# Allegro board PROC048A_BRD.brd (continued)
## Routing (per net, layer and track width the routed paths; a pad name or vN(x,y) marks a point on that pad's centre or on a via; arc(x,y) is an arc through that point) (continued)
ETH_D3N: length 20.9
  TOP w0.102: U6.14 71.81,62.57 71.85,62.53 72.48,62.53 73.91,63.95 75.25,63.95 76.29,62.91 76.74,62.91 76.99,63.17 76.99,63.83 76.89,63.93 v1(76.73,63.93)
  BOTTOM w0.102: v1(76.73,63.93) 77.03,63.62 77.03,62.91 77.54,62.4 77.54,61.74 77.03,61.24 77.03,59.69 77.39,59.33 78.09,59.33 U17.9 U17.2 79.41,59.22 79.52,59.33 79.88,59.33 80.99,58.21 83.03,58.21 83.53,58.72 83.76,58.76 J6.4
ETH_D3P: length 20.9
  TOP w0.102: U6.13 71.77,62.07 71.85,62.15 72.5,62.15 74.02,63.67 75.14,63.67 76.18,62.63 76.85,62.63 77.27,63.05 77.27,63.58 v1(77.62,63.93)
  BOTTOM w0.102: J6.3 83.23,59.03 83.26,58.99 83.26,58.85 82.91,58.49 81.11,58.49 79.99,59.61 79.52,59.61 79.41,59.72 U17.1 U17.10 78.09,59.61 77.5,59.61 77.31,59.8 77.31,61.12 77.82,61.63 77.82,62.52 77.31,63.03 77.31,63.62 v1(77.62,63.93)
ETH_INT: length 36
  TOP w0.14: U6.60 67.63,53.29 69.32,51.6 R58.2 70.33,51.6 70.53,51.4 v1(70.53,50.95) ; U12.A15 v1(47.4,41.91)
  BOTTOM w0.14: v1(70.53,50.95) 70.05,50.95 68.55,49.45 66.9,49.45 65.63,50.72 59.66,50.72 58.07,49.13 50.2,49.13 48.24,47.18 48.24,43.37 47.4,42.53 v1(47.4,41.91)
FB1_REGA: length 4.7
  TOP w0.381: C5.2 R10.2 R18.1 31.99,89.33 31.34,89.33 30.94,88.94 U1.1
FB1_REGB: length 4.7
  TOP w0.381: U2.1 55.71,88.94 56.1,89.33 56.76,89.33 R19.1 R11.2 C6.2
FB2_REGA: length 4.1
  TOP w0.381: C10.2 R12.2 R13.1 U1.8
FB2_REGB: length 4.1
  TOP w0.381: U2.8 R15.1 R14.2 C11.2
FPGA_DDR3_CLK_IN_N: length 7.9
  TOP w0.14: U12.A5 39,43.31 38.19,44.12 36.67,44.12 35.99,44.79 R71.2 35.99,46.23 36.2,46.44 U8.5
FPGA_DDR3_CLK_IN_P: length 7.7
  TOP w0.14: U8.4 R71.1 35.15,44.87 36.39,43.63 37.66,43.63 38.2,43.09 U12.A4
FPGA_ERR_LED2: length 77.8
  TOP w0.14: v1(11.4,90.6) 11.4,92.5 11.72,92.82 LD5.1 ; U12.D10 v1(42.6,39.51)
  L03_SIG1 w0.107: v1(11.4,90.6) 11.4,90.22 27.53,74.09 42.89,74.09 43.91,73.07 43.91,58.34 43.58,58.01 43.58,42.39 43.43,42.23 43.43,41.31 43.43,39.95 42.99,39.51 v1(42.6,39.51)
FPGA_HOST_INT: length 45.2
  TOP w0.14: R97.1 7.95,34.19 7.59,33.83 v1(7.59,32.05) ; U12.M3 v1(37,32.31)
  L03_SIG1 w0.107: v1(7.59,32.05) 7.59,28.24 11.02,24.81 14.95,24.81 16.22,23.54 v1(28.29,23.54)
  L08_SIG2 w0.107: v1(28.29,23.54) 28.03,23.8 28.03,27.1 29.18,28.24 30.96,28.24 34.64,31.92 36.61,31.92 v1(37,32.31)
FPGA_MCU_RSTN: length 25.4
  TOP w0.14: U13.1 40.88,18.64 41.04,18.48 R147.2 41.53,18.22 41.39,18.08 v1(39.46,18.08) ; v1(33.88,19.86) 34.38,20.37 34.38,24.43 33.5,25.32 33.5,28.88 v1(34.38,29.76) ; U12.N3 v1(37,31.51)
  L08_SIG2 w0.107: v1(37,31.51) 35.25,31.51 34.38,30.65 v1(34.38,29.76)
  BOTTOM w0.14: v1(39.46,18.08) 38.45,19.1 34.64,19.1 v1(33.88,19.86)
FPGA_RST: length 80.5
  TOP w0.14: R161.1 R162.2 C96.2 v1(25.09,6.38) ; U12.R1 35.7,30.31 v1(35.34,29.96) ; LD13.1 4.41,34.15 v1(4.41,33.07)
  L03_SIG1 w0.107: v1(35.34,29.96) 35.78,29.51 35.78,29 35.27,28.49 35.27,27.73 34.77,27.22 34.77,22.02 33.24,20.49 32.99,20.49 27.16,14.67 27.16,8.45 v1(25.09,6.38)
  BOTTOM w0.14: v1(35.34,29.96) 34.45,29.07 31.91,29.07 30.32,27.48 30.32,23.41 28.8,21.89 20.02,21.89 17.48,19.35 11.78,19.35 4.41,26.72 v1(4.41,33.07)
FPGA_SPI_CS: length 29.7
  TOP w0.14: v1(26.76,41.45) 26.51,41.19 R86.1 ; U12.E13 v1(45.8,38.71)
  L08_SIG2 w0.107: v1(26.76,41.45) 26.76,43.61 29.69,46.53 35.91,46.53 39.8,42.64 39.8,39.24 39.92,39.11 41.22,39.11 41.38,38.95 41.38,38.59 41.64,38.33 45.42,38.33 v1(45.8,38.71)
FPGA_SPI_MISO: length 67.3
  TOP w0.14: v1(10.64,34.08) 11.01,33.7 R90.1 ; U12.D14 v1(46.6,39.51)
  L03_SIG1 w0.107: v1(10.64,34.08) 7.97,36.75 7.97,40.94 13.81,46.78 27.69,46.78 32.77,51.86 32.77,54.32 v1(33.24,54.8)
  BOTTOM w0.14: v1(33.24,54.8) 34.12,54.8 36.04,52.88 40.1,52.88 44.54,48.43 44.54,43.1 43.78,42.34 43.78,40.94 44.01,40.71 45.17,40.71 45.4,40.48 45.4,40.15 45.64,39.92 46.2,39.92 46.6,39.52 v1(46.6,39.51)
FPGA_SPI_MOSI: length 49.6
  TOP w0.14: U12.C14 v1(46.6,40.31) ; R99.1 29.79,36.14 29.56,36.37 28.29,36.37 27.78,36.88 27.78,44.62 32.73,49.58 32.73,55.42 v1(33.11,55.8)
  BOTTOM w0.14: v1(33.11,55.8) 35.02,55.8 36.06,54.76 40.88,54.76 45.69,49.96 45.69,43.1 46.2,42.59 46.2,40.72 v1(46.6,40.31)
FPGA_SPI_SCK: length 48.8
  TOP w0.14: U12.A14 v1(46.6,41.91) ; R92.1 27.27,36.52 27.27,46.4 31.46,50.59 31.46,55.79 v1(32.04,56.37)
  BOTTOM w0.14: v1(32.04,56.37) 36.36,56.37 36.8,55.93 41.12,55.93 46.83,50.21 46.83,43.23 46.6,43 v1(46.6,41.91)
FPGA_UART_RX: length 38.3
  TOP w0.14: R142.1 v1(28.42,18.34) ; U12.A13 v1(45.8,41.91)
  L03_SIG1 w0.107: v1(34.45,18.65) 36.67,20.87 36.67,25.04 38.22,26.59 38.22,30.07 38.44,30.3 38.72,30.3 38.98,30.56 38.98,37.23 39.26,37.51 42.74,37.51 43.15,37.92 43.15,38.2 44.08,39.13 44.36,39.13 45.38,40.16 45.38,41.49 v1(45.8,41.91)
  BOTTOM w0.14: v1(34.45,18.65) 33.88,19.22 29.3,19.22 v1(28.42,18.34)
FPGA_UART_TX: length 73.9
  TOP w0.14: v1(32.73,17.95) 33.08,18.3 R139.1 ; U12.B13 v1(45.8,41.11)
  L08_SIG2 w0.107: v1(32.73,17.95) 32.73,18.39 31.9,19.22 27.78,19.22 27.27,19.73 27.27,33.07 23.84,36.5 23.84,49.96 29.18,55.29 v1(32.18,55.29)
  BOTTOM w0.14: v1(45.8,41.11) 45.05,41.86 45.05,49.2 40.73,53.51 36.16,53.51 34.38,55.29 v1(32.18,55.29)
FT_FPGA_RF_EP_I2C_SCL: length 143.3
  TOP w0.14: U7.6 v1(36.16,55.42) R51.2 36.89,54.92 37.11,54.69 39.18,54.69 43.15,50.72 47.85,50.72 49.37,49.2 49.37,46.66 49.12,46.41 R68.2 48.61,45.74 48.62,45.73 R81.1 ; R141.1 26.04,18.84 26.42,19.22 29.3,19.22 v1(29.81,19.73) ; v1(78.71,93.01) 78.72,93 R3.1
  L08_SIG2 w0.107: v1(78.71,93.01) 77.31,91.61 73.25,91.61 68.04,86.41 68.04,83.23 67.02,82.22 51.15,82.22 44.29,75.36 40.86,75.36 36.8,71.29 36.8,57.96 36.16,57.32 v1(36.16,55.42) 36.67,54.91 36.67,52.88 35.43,51.64 28.19,51.64 24.73,48.18 24.73,37 27.78,33.96 27.78,21.76 v1(29.81,19.73)
FT_FPGA_RF_EP_I2C_SDA: length 139.1
  TOP w0.14: v1(36.16,54.15) U7.5 ; v1(36.16,54.15) 36.16,53.7 36.31,53.55 39.3,53.55 42.51,50.34 47.21,50.34 47.97,49.58 47.97,46.54 47.84,46.41 R67.2 47.34,45.92 47.35,45.91 R76.1 ; v1(36.16,54.15) 36.42,54.15 R52.2 ; R136.1 25.77,19.73 v1(28.03,19.73) ; v1(76.42,93.14) R4.1 R5.1
  L08_SIG2 w0.107: v1(28.03,19.73) 27.53,20.24 27.53,33.45 24.22,36.75 24.22,48.27 30.11,54.15 v1(36.16,54.15) 36.16,54.66 35.53,55.29 35.53,72.06 39.34,75.87 44.04,75.87 51.02,82.85 66.01,82.85 67.53,84.37 67.53,86.79 72.99,92.25 75.53,92.25 v1(76.42,93.14)
FTDI1_VDD_1V8: length 7.2
  TOP w0.305: U15.12 v1(78.64,15.99) ; U15.64 v1(75.47,7.35) ; U15.37 v1(64.85,15.99) ; U15.49 67.97,7.6 67.15,6.78 C97.1
  TOP w0.381: C97.1 66.64,6.84 v1(66.64,7.79)
FTDI1_VPHY: length 5.4
  TOP w0.33: U15.4 78.82,11.99 79.13,12.3 C88.1
  TOP w0.381: C88.1 C90.1 82.62,12.3 FB4.2
FTDI1_VPLL: length 6.1
  TOP w0.305: 79.19,14.83 79.19,14.75 78.86,14.42 78.39,14.42 78.31,14.49 U15.9
  TOP w0.381: 79.19,14.83 79.19,15.17 79.77,15.75 C86.1 C85.1 FB3.2
FTDI2_VCORE: length 12.3
  TOP w0.254: U3.37 C15.1 70.95,86.03 71.34,86.41 v1(71.6,86.41) ; v1(74.77,76.25) 74.1,76.25 C32.1 74.03,76.65 74.7,77.32 U3.49 ; C14.1 85.98,86.44 84.99,85.45 U3.12 ; U3.64 82.2,77.58 82.94,76.84 C30.1
  TOP w0.381: v1(86.96,87.04) 86.58,86.66 86.32,86.66 C14.1 ; v1(82.26,76.37) C30.1
FTDI2_VPHY: length 5.3
  TOP w0.254: C23.1 85.73,81.02 85.31,81.45 U3.4
  TOP w0.381: C23.1 86.38,80.97 C24.1 88.91,80.97 89.07,80.81 FB2.2
FTDI2_VPLL: length 5.4
  TOP w0.254: U3.9 85.46,83.95 85.9,84.38 C17.1
  TOP w0.381: C17.1 86.46,84.38 86.74,84.66 C16.1 FB1.2
FTDI_HOST_INT: length 104
  TOP w0.14: v1(8.22,33.32) 8.5,33.05 R100.1 ; R6.1 71.14,92.17 70.61,91.65 R22.1 v1(66.9,87.79)
  L08_SIG2 w0.107: v1(66.9,87.79) 52.53,87.79 43.53,78.79 36.54,78.79 26.38,68.63 26.38,56.69 20.41,50.72 20.41,42.21 11.52,33.32 v1(8.22,33.32)
FTDI_JTAG_ACT: length 70.2
  TOP w0.14: v1(7.73,12.99) 8.28,12.99 LD15.1 ; U15.21 v1(73.47,18.74)
  BOTTOM w0.14: v1(73.47,18.74) 72.68,17.95 41.24,17.95 36.92,13.64 8.38,13.64 v1(7.73,12.99)
FTDI_JTAG_TCK: length 73.5
  TOP w0.14: TP9.1 90.26,20.8 89.46,20 R135.1 88.82,19.34 R140.2 ; U12.T5 v1(38.6,29.11)
  L08_SIG2 w0.107: v1(38.6,29.11) 39,29.51 40.48,29.51 40.61,29.38 40.61,24.68 40.92,24.38 76.62,24.38 79.47,27.22 84.8,27.22 85.18,27.61 87.85,27.61 88.64,26.82 88.64,24.08 TP9.1
FTDI_JTAG_TDI: length 56.5
  TOP w0.14: R124.2 v1(78.45,22.14) ; U12.R5 v1(38.6,29.91) ; R133.1 TP7.1
  L08_SIG2 w0.107: v1(78.45,22.14) 76.17,22.14 74.26,24.05 40.61,24.05 39.82,24.84 39.82,28.43 39.56,28.7 38.48,28.7 38.22,28.96 38.22,29.53 v1(38.6,29.91)
  BOTTOM w0.14: v1(78.45,22.14) 79.6,21 82.47,21 TP7.1
FTDI_JTAG_TDO: length 62
  TOP w0.14: R121.2 78.38,23.29 79.02,23.92 v1(79.47,23.92) 85.62,23.92 TP8.1 R134.1 ; U12.V4 v1(37.8,27.51)
  L08_SIG2 w0.107: v1(79.47,23.92) 79.34,23.8 79.34,21.76 78.33,20.75 74.01,20.75 72.1,22.65 54.07,22.65 53.31,23.41 39.08,23.41 38.38,24.12 38.38,25.27 38.22,25.42 38.22,27.1 v1(37.8,27.51)
FTDI_JTAG_TMS: length 55.9
  TOP w0.14: R118.2 R115.1 TP1.1 ; U12.U5 v1(38.6,28.31)
  L08_SIG2 w0.107: v1(38.6,28.31) 38.98,27.93 38.98,25.41 38.83,25.26 38.83,24.3 39.34,23.8 53.82,23.8 54.63,22.98 73.05,22.98 74.77,21.26 78.18,21.26 78.89,21.97 78.89,25.12 79.39,25.62 TP1.1
FTDI_MCU_RSTN: length 109.7
  TOP w0.14: U13.2 41.09,19.14 41.57,19.61 R144.2 41.57,20.55 41.37,20.75 35.02,20.75 34.77,21 34.77,24.56 33.88,25.45 33.88,28.75 34.13,29 34.38,29 34.84,29.46 34.84,32.23 v1(34.51,32.56) ; R26.1 67.97,80.9 v1(67.08,80.02)
  L08_SIG2 w0.107: v1(67.08,80.02) 50.98,80.02 39.03,68.07 39.03,57.74 39.04,57.73 39.04,53.87 39.03,53.86 39.03,51.17 36.16,48.31 29.05,48.31 25.75,45 25.75,40.69 26.13,40.31 26.13,37.13 28.54,34.72 31.97,34.72 34.13,32.56 v1(34.51,32.56)
FTDI_UART_RXD: length 107.7
  TOP w0.14: U3.38 71.92,84.95 71.34,84.37 67.02,84.37 v1(66.77,84.63) ; v1(29.18,17.95) 28.54,17.32 27.8,17.32 R146.1
  L08_SIG2 w0.107: v1(29.18,17.95) 28.67,17.95 28.54,17.83 27.91,17.83 27.02,18.72 27.02,32.43 23.46,35.99 23.46,50.59 29.56,56.69 29.56,67.23 38.83,76.5 43.78,76.5 50.77,83.49 65.63,83.49 v1(66.77,84.63)
FTDI_UART_TXD: length 112.3
  TOP w0.14: v1(65.5,84.63) 66.29,83.84 71.44,83.84 72.05,84.45 U3.39 ; R138.1 32.48,18.72 v1(31.97,18.21)
  L08_SIG2 w0.107: v1(65.5,84.63) 65.19,84.94 51.33,84.94 43.53,77.14 38.58,77.14 28.42,66.98 28.42,56.94 22.32,50.85 22.32,36.37 26.76,31.92 26.76,18.59 27.91,17.45 31.21,17.45 v1(31.97,18.21)
FTDI_USB1_DM: length 21.3
  TOP w0.102: J4.2 97.02,22.58 96.8,22.8 96.43,22.8 96.42,22.8 96.28,22.8 96.04,22.56 D11.1 95.57,22.56 95.49,22.63 95.37,22.63 93.87,21.13 92.93,21.13 90.43,18.63 88.4,18.63 83.79,14.02 80.88,14.02 80.78,13.92 R152.1
FTDI_USB1_DM_C: length 3
  TOP w0.102: R152.2 79.94,13.83 79.84,13.93 79.48,13.93 79.38,13.93 79.09,13.63 78.49,13.63 78.35,13.49 U15.7
FTDI_USB1_DP: length 21.2
  TOP w0.102: R150.1 81.2,14.23 83.7,14.23 88.31,18.84 90.34,18.84 92.84,21.34 93.78,21.34 95.34,22.91 95.34,23.03 95.57,23.26 D11.2 96.04,23.26 96.28,23.01 96.51,23.01 96.52,23.01 96.8,23.01 97.02,23.23 J4.3
FTDI_USB1_DP_C: length 3.1
  TOP w0.102: U15.8 78.35,13.99 78.49,13.85 79,13.85 79.32,14.17 79.84,14.17 79.94,14.27 R150.2
FTDI_USB2_DM: length 20.2
  TOP w0.102: R24.1 88.36,82.98 91.28,82.98 92.46,81.8 92.46,75.83 94.84,73.45 94.84,72.34 95.08,72.1 95.08,71.95 95.31,71.72 D9.1 95.52,71.72 95.85,72.06 96.04,72.06 96.15,71.95 96.15,71.2 96.44,70.91 96.83,70.91 97.02,70.73 J1.2
FTDI_USB2_DM_C: length 3.3
  TOP w0.102: R24.2 86.73,82.85 86.02,82.85 85.78,83.09 85,83.09 84.86,82.95 U3.7
FTDI_USB2_DP: length 19.9
  TOP w0.102: J1.3 97.02,71.38 96.77,71.13 96.53,71.13 96.36,71.29 96.36,72.04 96.13,72.27 95.64,72.27 95.49,72.42 D9.2 95.33,72.42 95.26,72.35 95.14,72.35 95.05,72.43 95.05,73.54 92.68,75.92 92.68,81.89 91.37,83.19 88.27,83.19 R23.1
FTDI_USB2_DP_C: length 3.5
  TOP w0.102: R23.2 87.05,83.19 86.92,83.07 86.11,83.07 85.87,83.31 85,83.31 84.86,83.45 U3.8
GPIO_PHY_RESETN: length 32.8
  TOP w0.14: 68.48,51.54 67.98,51.54 67.79,51.35 67.79,49.83 v1(66.9,48.94) ; 68.48,51.54 68.48,51.93 67.15,53.26 67.15,54.1 U6.59 ; 68.48,51.54 R57.2 ; U12.A16 48.2,41.91 v1(48.2,42.59)
  BOTTOM w0.14: v1(66.9,48.94) 64.48,48.94 64.1,49.32 64.1,49.96 63.72,50.34 60.55,50.34 58.26,48.05 50.39,48.05 49.24,46.91 49.24,43.48 48.35,42.59 v1(48.2,42.59)
HEADER_ERR_LED4: length 75.2
  TOP w0.14: LD8.1 v1(17.37,93.65) ; U12.B11 v1(44.2,41.11)
  L03_SIG1 w0.107: v1(44.2,41.11) 44.54,41.45 44.54,41.71 45.56,42.73 45.56,57.32 46.11,57.88 46.11,74.42 43.02,77.52 29.18,77.52 16.86,89.84 16.86,93.14 v1(17.37,93.65)
HOST_INT: length 7.5
  TOP w0.14: R100.2 R97.2 10.31,34.59 12.92,34.59 13.98,33.54 J3.10
INITN: length 128.9
  TOP w0.14: LD12.1 3.74,38.74 3.65,38.65 v1(3.27,38.65) ; R111.2 87.75,27.63 87.09,26.97 TP3.1 ; U12.V3 v1(37,27.51)
  L08_SIG2 w0.107: v1(37,27.51) 36.62,27.13 36.62,22.96 38.07,21.51 39.85,21.51 40.48,20.87 55.63,20.87 56.26,21.51 64.99,21.51 67.28,19.22 83.66,19.22 85.57,21.13 85.57,25.45 85.74,25.62 TP3.1
  BOTTOM w0.14: v1(3.27,38.65) 3.02,38.4 3.02,22.4 4.41,21 8.73,21 11.14,18.59 18,18.59 20.16,20.75 29.94,20.75 30.7,19.99 33.24,19.99 35.02,21.76 35.02,25.07 36.27,26.32 37.17,26.32 37.4,26.55 37.4,27.11 v1(37,27.51)
LED_ACTN: length 34.2
  TOP w0.14: U6.61 68.13,53.3 69.18,52.24 70.45,52.24 71.98,50.72 77.82,50.72 v1(78.71,51.61)
  L08_SIG2 w0.107: v1(78.71,51.61) 78.71,50.72 82.52,46.91 94.33,46.91 95.52,48.1 95.52,49.71 J6.12
LED_LINKN: length 40.1
  TOP w0.14: v1(77.82,52.5) 76.68,51.35 71.98,51.35 70.71,52.62 69.31,52.62 68.63,53.3 U6.62
  L08_SIG2 w0.107: v1(77.82,52.5) 79.09,53.77 79.09,63.04 82.01,65.96 92.42,65.96 93.49,64.89 J6.13
LED_SPEED: length 5.5
  TOP w0.14: U6.63 69.13,53.31 69.44,53.01 71.42,53.01 v1(71.93,52.5)
  BOTTOM w0.14: v1(71.93,52.5) 72.23,52.19 TP12.1
LVDS_0M: length 48.6
  TOP w0.102: U12.E3 v1(37,38.71) ; J3.58 14.93,21.54 14.7,21.76 13.18,21.76 12.79,21.38 v1(12.79,21.3)
  BOTTOM w0.102: v1(37,38.71) 36.86,38.86 36.71,38.86 36.43,39.14 35.92,39.14 35.77,39.29 35.44,39.29 R203.2 34.88,39.26 32.6,39.26 26.27,32.94 23.86,32.94 21.45,30.53 13.19,30.53 12.16,29.5 12.16,28.11 12.92,27.35 12.92,25.57 13.56,24.94 15.72,24.94 16.35,24.3 16.35,22.14 15.97,21.76 12.39,21.76 12.29,21.66 12.29,21.4 12.39,21.3 v1(12.79,21.3)
LVDS_0P: length 48.6
  TOP w0.102: J3.56 14.82,22.04 14.82,22.04 12.97,22.04 v1(12.79,22.22) ; U12.F4 v1(37.8,37.91)
  BOTTOM w0.102: v1(12.79,22.22) 12.97,22.04 15.85,22.04 16.07,22.26 16.07,24.19 15.6,24.66 13.44,24.66 12.64,25.46 12.64,27.24 11.88,28 11.88,29.61 13.07,30.81 21.33,30.81 23.74,33.22 26.16,33.22 32.48,39.54 34.85,39.54 R203.1 35.41,39.57 35.88,39.57 36.04,39.42 36.54,39.42 36.83,39.14 37.12,39.14 37.38,38.87 37.38,38.34 v1(37.8,37.91)
LVDS_1M: length 48.8
  TOP w0.102: v1(13.56,22.85) 13.84,23.14 14.7,23.14 14.8,23.04 J3.52 ; U12.D5 v1(38.6,39.51)
  BOTTOM w0.102: v1(38.6,39.51) 38.47,39.64 38.47,40.17 36.05,42.59 35.31,42.59 R198.2 34.88,42.49 34.64,42.51 33.42,42.51 32.51,41.6 32.24,41.6 28.68,38.05 28.05,38.05 24.97,34.97 21.16,34.97 20.11,33.92 12.36,33.92 9.59,31.15 9.59,25.84 11.54,23.9 11.79,23.9 12.68,23.01 13.41,23.01 v1(13.56,22.85)
LVDS_1P: length 48.9
  TOP w0.102: U12.E4 v1(37.8,38.71) ; J3.50 14.8,23.54 14.68,23.41 13.68,23.41 13.56,23.54 v1(13.56,23.72)
  BOTTOM w0.102: v1(37.8,38.71) 38.19,39.11 38.19,40.05 35.93,42.31 35.54,42.31 R198.1 34.85,42.21 34.62,42.23 33.53,42.23 32.62,41.32 32.35,41.32 28.8,37.77 28.16,37.77 25.09,34.69 21.28,34.69 20.22,33.64 12.48,33.64 9.87,31.03 9.87,25.95 11.65,24.18 11.91,24.18 12.79,23.29 13.46,23.29 13.56,23.39 v1(13.56,23.72)
LVDS_2M: length 49
  TOP w0.102: v1(9.24,24.98) 9.24,24.91 9.14,24.81 8.9,24.81 8.76,24.96 8.76,25.47 9.09,25.8 12.77,25.8 13.11,26.15 14.69,26.15 14.8,26.04 J3.40 ; U12.E1 35.8,38.58 35.42,38.96 35.42,39.27 34.14,40.55 33.4,40.55 R84.2 32.83,40.55 32.45,40.55 31.43,41.58 31.27,41.58 v1(30.96,41.26)
  BOTTOM w0.102: v1(9.24,24.98) 9.11,24.84 8.96,24.84 8.73,25.08 8.73,31.03 13.3,35.61 24.35,35.61 28.39,39.65 29.17,39.65 30.47,40.95 30.47,41.45 30.57,41.55 30.85,41.55 30.96,41.45 v1(30.96,41.26)
LVDS_2P: length 49
  TOP w0.102: v1(30.96,42.12) 31.22,41.86 31.54,41.86 32.57,40.83 32.83,40.83 R84.1 33.4,40.83 34.26,40.83 35.59,39.49 35.96,39.49 36.34,39.11 U12.D2 ; J3.38 14.8,26.54 14.69,26.43 13,26.43 12.65,26.08 8.97,26.08 8.48,25.59 8.48,25.14 v1(8.31,24.98)
  BOTTOM w0.102: v1(30.96,42.12) 30.66,41.83 30.46,41.83 30.19,41.56 30.19,41.07 29.05,39.92 28.27,39.92 24.24,35.89 13.19,35.89 8.45,31.15 8.45,25.12 v1(8.31,24.98)
LVDS_3M: length 48.9
  TOP w0.102: J3.34 14.8,27.54 14.69,27.65 13.06,27.65 11.32,29.38 8.2,29.38 8.1,29.28 8.1,28.37 8.32,28.14 10.48,28.14 10.89,27.73 10.89,26.97 11.02,26.84 11.3,26.84 v1(11.34,26.88) ; U12.D3 v1(37,39.51)
  BOTTOM w0.102: v1(37,39.51) 36.72,39.8 36.4,39.8 35.79,40.41 34.9,40.41 34.47,40.84 34.33,40.84 R200.2 33.72,40.8 33.48,40.8 33.09,40.41 32.6,40.41 26.02,33.83 22.7,33.83 21.53,32.66 14.18,32.66 10.89,29.37 10.89,26.88 11.04,26.73 11.19,26.73 v1(11.34,26.88)
LVDS_3P: length 48.9
  TOP w0.102: J3.32 14.8,28.04 14.69,27.93 13.18,27.93 11.44,29.66 8.08,29.66 7.82,29.4 7.82,28.25 8.21,27.86 10.37,27.86 10.61,27.62 10.61,27.05 v1(10.44,26.88) ; U12.C3 v1(37,40.31)
  BOTTOM w0.102: v1(10.44,26.88) 10.61,27.05 10.61,29.49 14.06,32.94 21.42,32.94 22.59,34.11 25.9,34.11 32.48,40.69 32.97,40.69 33.48,41.19 33.84,41.19 R200.1 34.17,41.19 34.51,41.19 35.02,40.69 35.91,40.69 36.52,40.08 36.77,40.08 v1(37,40.31)
LVDS_12BIT_MODE_ON: length 73.6
  TOP w0.14: U12.A6 39.8,51.65 38.62,52.83 36.63,52.83 36.16,52.37 v1(35.53,52.37) ; v1(7.84,82.85) SW1.1
  L03_SIG1 w0.107: v1(35.53,52.37) 35.53,55.8 32.99,58.34 23.34,58.34 12.54,69.13 7.84,69.13 3.9,73.07 3.9,82.09 4.67,82.85 v1(7.84,82.85)
  BOTTOM w0.14: R223.1 6.23,83.47 6.85,82.85 v1(7.84,82.85)
LVDS_14BIT_MODE_ON: length 62.7
  TOP w0.14: v1(33.75,62.28) 33.8,62.23 33.8,45.46 36.06,43.21 37.02,43.21 37.8,42.43 37.8,41.35 38.03,41.12 39.4,41.12 U12.B6 ; SW1.2 v1(8.48,81.58)
  L03_SIG1 w0.107: v1(33.75,62.28) 33.5,62.28 14.83,80.95 10,80.95 9.37,81.58 v1(8.48,81.58)
  BOTTOM w0.14: R222.1 v1(8.48,81.58)
LVDS_16BIT_MODE_ON: length 72.7
  TOP w0.14: U12.D7 v1(40.2,39.51) ; SW1.3 v1(7.97,80.31)
  L03_SIG1 w0.107: v1(40.05,60.4) 40.05,68.43 37.69,70.79 26,70.79 14.57,82.22 8.08,82.22 7.71,81.86 7.71,80.56 v1(7.97,80.31)
  L08_SIG2 w0.107: v1(40.2,39.51) 40.2,39.52 40.58,39.9 40.58,42.89 40.05,43.43 v1(40.05,60.4)
  BOTTOM w0.14: R224.1 v1(7.97,80.31)
LVDS_CAPTURE: length 55.2
  TOP w0.14: SW2.1 13.94,72.65 14.08,72.79 v1(14.45,72.79) ; U12.E8 v1(41,38.71)
  L03_SIG1 w0.107: v1(14.45,72.79) 14.19,72.54 14.19,69.01 23.84,59.36 34,59.36 37.18,56.18 37.18,53.13 36.54,52.5 36.54,43.71 39.82,40.43 39.82,40.16 40.04,39.93 40.35,39.93 40.61,39.67 40.61,39.11 v1(41,38.71)
  BOTTOM w0.14: R173.2 13.94,72.65 14.08,72.79 v1(14.45,72.79)
LVDS_CLKM: length 49.1
  TOP w0.102: U12.F3 v1(37,37.91) ; v1(11.59,23.19) 11.27,23.19 11.17,23.29 11.17,23.95 11.98,24.76 14.63,24.76 14.85,24.54 J3.46
  BOTTOM w0.102: v1(37,37.91) 36.74,37.65 36.48,37.65 35.99,37.16 35.54,37.16 R208.2 34.73,37.13 32.48,37.13 25.49,30.15 25.49,23.33 25.39,23.23 24.83,23.23 24.73,23.33 24.73,24.44 24.47,24.7 23.8,24.7 23.54,24.44 23.54,23.36 23.21,23.03 18.75,23.03 16.21,20.49 11.91,20.49 11.17,21.23 11.17,23.09 11.3,23.21 11.56,23.21 v1(11.59,23.19)
LVDS_CLKP: length 49.1
  TOP w0.102: v1(10.72,23.19) 10.89,23.35 10.89,24.06 11.86,25.04 J3.44 ; U12.G3 v1(37,37.11)
  BOTTOM w0.102: v1(10.72,23.19) 10.89,23.02 10.89,21.11 11.79,20.21 16.33,20.21 18.87,22.75 23.32,22.75 23.82,23.25 23.82,24.32 23.92,24.42 24.35,24.42 24.45,24.32 24.45,23.22 24.72,22.95 25.51,22.95 25.77,23.22 25.77,30.03 32.6,36.85 35.01,36.85 R208.1 35.31,36.88 36.1,36.88 36.6,37.37 36.74,37.37 v1(37,37.11)
LVDS_FRCLKN: length 49.1
  TOP w0.102: v1(13.56,28.75) 13.56,29.03 13.66,29.13 15.59,29.13 J3.28 ; U12.E2 v1(36.2,38.71)
  BOTTOM w0.102: v1(36.2,38.71) 35.94,38.45 33.61,38.45 R204.2 33.09,38.41 32.62,38.41 24.58,30.37 24.58,28.98 24.22,28.62 22.94,28.62 22.42,28.1 22.42,24.55 22.08,24.2 20.92,24.2 20.67,24.46 20.67,26.34 20.29,26.72 19.51,26.72 19.14,26.35 19.14,24.43 18.92,24.2 17.6,24.2 17.37,24.43 17.37,29.5 16.97,29.89 15.57,29.89 15.21,29.53 15.21,28.11 15.08,27.99 13.43,27.99 13.02,28.39 13.02,29.16 13.12,29.26 13.81,29.26 13.91,29.16 13.91,29.01 13.65,28.75 v1(13.56,28.75)
LVDS_FRCLKP: length 49
  TOP w0.102: v1(13.56,29.72) 13.56,29.63 13.77,29.43 15.57,29.43 J3.26 ; U12.F2 v1(36.2,37.91)
  BOTTOM w0.102: v1(13.56,29.72) 13.38,29.54 13.01,29.54 12.74,29.27 12.74,28.28 13.31,27.71 15.2,27.71 15.49,28 15.49,29.41 15.69,29.61 16.86,29.61 17.09,29.38 17.09,24.32 17.48,23.92 19.03,23.92 19.42,24.32 19.42,26.23 19.63,26.44 20.17,26.44 20.39,26.22 20.39,24.34 20.81,23.92 22.19,23.92 22.7,24.43 22.7,27.99 23.06,28.34 24.34,28.34 24.86,28.86 24.86,30.26 32.74,38.13 33.09,38.13 R204.1 33.69,38.17 36.03,38.17 36.2,38.01 v1(36.2,37.91)
LVDS_PATH_ERR_LED3: length 74.5
  TOP w0.14: U12.A11 v1(44.2,41.91) ; LD7.1 v1(14.19,93.65)
  L03_SIG1 w0.107: v1(14.19,93.65) 14.95,92.88 14.95,90.47 29.05,76.37 42.89,76.37 45.24,74.02 45.24,42.96 v1(44.2,41.91)
LVDS_VALIDM: length 48.8
  TOP w0.102: v1(10.76,30.35) 11.06,30.65 14.69,30.65 14.8,30.54 J3.22 ; U12.B3 37.4,40.98 37.02,41.36 37.02,41.97 36.56,42.44 33.38,42.44 R82.2 32.85,42.44 32.49,42.44 v1(32.19,42.13)
  L03_SIG1 w0.089: v1(10.76,30.35) 10.94,30.53 15.33,30.53 15.59,30.79 15.59,32.05 15.68,32.14 16.24,32.14 16.33,32.05 16.33,30.79 16.63,30.49 17.61,30.49 18.13,31 18.13,42.34 19.24,43.45 30.45,43.45 31.6,42.3 32.02,42.3 v1(32.19,42.13)
LVDS_VALIDP: length 48.8
  TOP w0.102: v1(10.76,31.22) 11.06,30.93 14.69,30.93 14.8,31.04 J3.20 ; v1(32.19,43.02) 32.49,42.72 32.82,42.72 R82.1 33.41,42.72 36.67,42.72 37.31,42.08 37.31,41.61 U12.A3
  L03_SIG1 w0.089: v1(10.76,31.22) 10.76,30.91 10.85,30.82 15.21,30.82 15.3,30.91 15.3,32.17 15.56,32.43 16.36,32.43 16.62,32.17 16.62,30.91 16.75,30.78 17.49,30.78 17.84,31.12 17.84,42.46 19.12,43.74 30.57,43.74 31.72,42.59 31.84,42.59 32.19,42.94 v1(32.19,43.02)
MCU_RSTN: length 20.3
  TOP w0.14: J3.59 22.67,21.04 22.83,20.87 22.83,17.83 24.35,16.3 30.35,16.3 30.73,16.68 32.73,16.68 34.13,18.08 34.64,18.08 35.15,18.59 35.15,19.35 35.43,19.64 R143.2
MDIO_MDC: length 40.7
  TOP w0.14: v1(68.18,64.34) 68.18,64.68 68.13,64.73 U6.20 ; v1(46.32,45.87) 46.2,45.74 R75.1
  L08_SIG2 w0.107: v1(46.32,45.87) 45.81,46.38 45.81,48.05 46.83,49.07 46.83,59.99 50.39,63.55 53.82,63.55 54.61,64.34 v1(68.18,64.34)
  BOTTOM w0.14: v1(68.18,64.34) R183.2
MDIO_MDIO: length 47.2
  TOP w0.14: v1(46.33,49.7) 46.33,49.08 43.91,46.66 R73.1 ; U6.21 67.66,65.55 67.66,66.46 v1(68.18,66.98)
  L08_SIG2 w0.107: v1(46.33,49.7) 46.33,65.25 46.67,65.58 66.78,65.58 v1(68.18,66.98)
  BOTTOM w0.14: R181.2 68.34,65.78 68.18,65.95 v1(68.18,66.98)
MEM_VREF: length 5.8
  TOP w0.356: U10.J8 v1(61.09,38.08) ; U10.E1 v1(66.69,34.88) ; U11.E1 v1(78.5,34.88) ; U11.J8 v1(72.1,38.88)
  BOTTOM w0.33: 72.63,38.91 72.13,38.91 v1(72.1,38.88)
  BOTTOM w0.381: v1(61.09,38.08) 61.13,38.13 C140.2 ; v1(78.5,34.88) 78.64,35.02 79.44,35.02 C162.2 ; C139.1 72.63,38.91 ; C159.1 67.36,34.88 v1(66.69,34.88)
  vias: v1(86.33,44.75) v1(86.33,43.86)
OSC_CLKEN: length 15.7
  TOP w0.14: v1(39.31,43.86) 39.31,51.16 38.82,51.65 R54.1 ; U12.E5 v1(38.6,38.71)
  BOTTOM w0.14: v1(38.6,38.71) 39,39.11 39,41.15 38.19,41.96 38.19,43.58 38.47,43.86 v1(39.31,43.86)
PG: length 1.5
  BOTTOM w0.14: R201.2 93.69,39.6 93.81,39.48 U19.9
PGOOD: length 10.8
  TOP w0.14: v1(29.05,32.56) 29.05,33.44 28.66,33.83 R98.1 ; U12.L2 v1(36.2,33.11)
  BOTTOM w0.14: v1(36.2,33.11) 35.14,32.05 34.08,32.05 33.57,32.56 v1(29.05,32.56)
PHY_JTAG_RESET: length 3
  TOP w0.14: U6.24 66.08,65.57 66.08,66.38 65.87,66.59 65.25,66.59 64.99,66.85 64.99,67.48 65.04,67.53 R39.1
PROGRAMN: length 115.3
  TOP w0.14: v1(3.4,39.67) 3.4,40.63 3.54,40.77 LD11.1 ; R132.2 TP6.1 ; R114.1 R117.2 C81.2 3.63,22.68 v1(3.97,22.34) ; U12.W3 v1(37,26.71)
  L08_SIG2 w0.107: v1(37,26.71) 37.43,26.28 37.43,24.43 38.9,22.96 52.87,22.96 53.59,22.24 67.56,22.24 69.56,20.24 78.53,20.24 TP6.1
  BOTTOM w0.14: v1(37,26.71) 36.6,27.11 35.03,27.11 34.51,26.59 34.51,21.76 33.37,20.62 31.21,20.62 30.7,21.13 19.91,21.13 17.75,18.97 11.27,18.97 7.71,22.53 4.67,22.53 4.48,22.34 v1(3.97,22.34) 3.78,22.53 3.78,39.29 v1(3.4,39.67)
RAW_MODE: length 57
  TOP w0.14: SW2.4 10.13,72.56 10.36,72.79 v1(10.84,72.79) ; U12.C8 v1(41,40.31)
  L03_SIG1 w0.107: v1(41,40.31) 40.62,40.69 40.62,41.26 40.35,41.53 40.02,41.53 38.19,43.35 38.19,43.86 38.07,43.99 38.07,57.83 35.78,60.12 30.83,60.12 16.86,74.09 12.13,74.09 v1(10.84,72.79)
  BOTTOM w0.14: v1(10.84,72.79) 10.36,72.79 10.13,72.56 R176.2
RF_CONN_SPI_CS: length 110.1
  TOP w0.14: U3.19 81.2,88.29 v1(81.18,88.26) ; R85.1 v1(25.37,47.8)
  L08_SIG2 w0.107: v1(25.37,47.8) 28.32,50.75 35.05,50.75 37.31,53.01 37.31,71.04 41.12,74.85 44.54,74.85 51.15,81.45 67.15,81.45 68.67,82.98 68.67,86.03 71.85,89.2 79.09,89.2 79.37,88.92 79.37,82.7 79.47,82.6 80.38,82.6 80.49,82.7 80.49,90.49 80.59,90.6 81.07,90.6 81.18,90.49 v1(81.18,88.26)
RF_CONN_SPI_MISO: length 115.5
  TOP w0.14: v1(82.6,90.98) 82.27,91.31 R7.2 81.7,91.14 U3.18 ; R96.1 11.01,31.8 11.14,31.67 11.52,31.67 v1(11.78,31.42)
  L08_SIG2 w0.107: v1(11.78,31.42) 11.78,32.69 21.18,42.08 21.18,50.47 27.27,56.56 27.27,67.23 38.07,78.02 43.66,78.02 51.66,86.03 66.01,86.03 73.75,93.77 80.9,93.77 81.41,93.26 81.41,90.85 81.53,90.72 82.34,90.72 v1(82.6,90.98)
RF_CONN_SPI_MOSI: length 112.7
  TOP w0.14: R101.1 30.07,34.46 30.45,34.08 v1(30.45,33.96) ; v1(83.66,92.12) 83.66,90.98 83.15,90.47 82.52,90.47 82.2,90.16 U3.17
  L08_SIG2 w0.107: v1(83.66,92.12) 83.06,91.52 83.06,88.57 82.14,87.64 82.14,84.15 82.42,83.87 82.42,81.33 82.17,81.07 51.53,81.07 37.81,67.36 37.81,51.74 35.53,49.45 28.42,49.45 25.24,46.27 25.24,40.43 25.75,39.92 25.75,36.75 28.54,33.96 v1(30.45,33.96)
RF_CONN_SPI_SCK: length 115.2
  TOP w0.14: v1(84.93,88.31) 84.93,87.59 84.79,87.45 U3.16 ; R91.1 v1(26.64,37.26)
  L08_SIG2 w0.107: v1(84.93,88.31) 84.93,91.23 84.8,91.36 83.66,91.36 83.53,91.23 83.53,84.63 83.9,84.26 87.33,84.26 87.47,84.12 87.47,83.49 87.34,83.36 84.68,83.36 84.42,83.1 84.42,79.29 83.79,78.66 51.28,78.66 39.54,66.93 39.54,49.91 36.8,47.16 29.69,47.16 26.26,43.73 26.26,40.94 26.64,40.56 v1(26.64,37.26)
RGMII_CLKOUT: length 36
  TOP w0.14: U12.A19 v1(50.6,41.91)
  L08_SIG2 w0.107: v1(50.6,41.91) 50.6,43.31 50.89,43.61 55.72,43.61 59.15,47.04 59.15,48.81 59.91,49.58 59.91,62.66 61.05,63.8 v1(65.8,63.8)
  BOTTOM w0.14: R182.1 v1(65.8,63.8)
RGMII_RXC: length 25.2
  TOP w0.14: v1(52.86,58.66) 53.31,59.1 R47.1 ; U12.D11 v1(44.2,39.51)
  L08_SIG2 w0.107: v1(52.86,58.66) 49.5,55.29 49.5,47.54 44.61,42.66 44.61,39.92 v1(44.2,39.51)
RGMII_RXCTL: length 17.8
  TOP w0.14: U12.B20 v1(51.4,41.11) ; R63.1 63.38,50.37 63.52,50.23 v1(63.52,49.78)
  BOTTOM w0.14: v1(51.4,41.11) 54.4,44.12 58.26,44.12 63.52,49.37 v1(63.52,49.78)
RGMII_RXD0: length 25.8
  TOP w0.14: U12.B17 v1(49,41.11) ; v1(54.58,58.21) 54.83,58.21 55.72,57.32 R48.2
  L08_SIG2 w0.107: v1(49,41.11) 48.62,41.49 48.62,42.48 49.12,42.97 49.12,44.55 49.01,44.66 48.08,44.66 47.97,44.77 47.97,44.98 48.08,45.09 49.01,45.09 49.12,45.19 49.12,46.66 49.88,47.42 49.88,55.16 51.47,56.75 53.84,56.75 53.94,56.86 53.94,57.58 v1(54.58,58.21)
RGMII_RXD1: length 20.9
  TOP w0.14: R60.2 51.95,50.55 51.78,50.72 51.78,51.74 51.53,51.99 50.13,51.99 49.91,51.77 49.91,50.72 50.17,50.47 50.93,50.47 51.07,50.33 51.07,49.49 50.89,49.32 50.4,49.32 50.26,49.18 50.26,47.77 50.4,47.63 51.14,47.63 51.28,47.49 v1(51.28,47.04) ; U12.D16 v1(48.2,39.51)
  BOTTOM w0.14: v1(48.2,39.51) 48.2,40.88 48.84,41.51 49.31,41.51 51.53,43.73 51.53,46.78 v1(51.28,47.04)
RGMII_RXD2: length 21.6
  TOP w0.14: U12.A17 v1(49,41.91) ; R61.2 53.18,50.05 v1(53.18,46.91)
  L08_SIG2 w0.107: v1(53.18,46.91) 52.93,46.66 52.93,45.42 52.82,45.32 50.24,45.32 50.13,45.21 50.13,44.88 50.26,44.75 54.47,44.75 54.58,44.64 54.58,44.22 54.47,44.12 49.62,44.12 49.45,43.94 49.45,42.36 v1(49,41.91)
RGMII_RXD3: length 20.6
  TOP w0.14: U12.E15 v1(47.4,38.71) ; R62.2 54.5,50.22 54.5,47.92 54.64,47.78 56.51,47.78 56.65,47.64 56.65,47.36 56.51,47.22 54.84,47.22 54.7,47.08 54.7,46.4 v1(54.45,46.15)
  BOTTOM w0.14: v1(54.45,46.15) 54.45,45.13 50.03,40.71 48.84,40.71 48.6,40.47 48.6,38.9 48.41,38.71 v1(47.4,38.71)
RGMII_TXC: length 29.2
  TOP w0.14: U6.40 60.14,60.12 59.15,60.12 58.26,61.01 58.26,61.13 57.12,62.28 53.92,62.28 v1(53.31,62.28) ; v1(46.32,47.9) 45.05,46.63 R74.1
  L08_SIG2 w0.107: v1(46.32,47.9) 47.19,47.9 48.99,49.7 48.99,58.47 52.8,62.28 v1(53.31,62.28)
RGMII_TXCTL: length 26.9
  TOP w0.14: v1(61.18,49.78) 61.82,50.42 61.82,51.23 63.63,53.04 63.63,54.12 ; U12.D15 v1(47.4,39.51)
  BOTTOM w0.14: v1(61.18,49.78) 61,49.78 58.9,47.67 51.15,47.67 50.39,46.91 50.39,43.23 49.75,42.59 49.12,42.59 47.85,41.32 47.85,39.96 v1(47.4,39.51)
RGMII_TXD0: length 27.7
  TOP w0.14: U6.38 60.12,61.01 v1(59.02,61.01) ; v1(53.43,45.89) R80.1
  L08_SIG2 w0.107: v1(59.02,61.01) 59.28,60.75 59.28,55.16 58.26,54.15 58.26,47.8 57.44,46.97 56.76,46.97 56.65,46.87 56.65,45.37 56.54,45.26 56.33,45.26 56.22,45.37 56.22,46.87 56.12,46.97 55.9,46.97 55.8,46.87 55.8,45.37 55.69,45.26 55.48,45.26 55.37,45.37 55.37,46.87 55.2,47.04 54.58,47.04 v1(53.43,45.89)
RGMII_TXD1: length 29.4
  TOP w0.14: v1(51,45.87) 51.15,45.72 R78.1 ; v1(58.77,61.77) 58.9,61.64 60.11,61.64 U6.37
  L08_SIG2 w0.107: v1(58.77,61.77) 58.77,62.02 58.01,62.78 57.37,62.78 56.48,61.9 56.48,60.63 56.99,60.12 56.99,47.67 56.74,47.42 54.83,47.42 54.68,47.57 54.68,48.2 54.57,48.31 54.36,48.31 54.25,48.2 54.25,47.78 54.14,47.67 53.93,47.67 53.82,47.78 53.82,48.2 53.72,48.31 53.5,48.31 53.4,48.2 53.4,47.65 53.29,47.54 52.16,47.54 51.91,47.29 51.91,46.78 v1(51,45.87)
RGMII_TXD2: length 27.9
  TOP w0.14: v1(55.09,62.78) 58.51,62.78 59.23,62.07 U6.36 ; v1(49.83,45.87) 49.88,45.82 R77.1
  L08_SIG2 w0.107: v1(49.83,45.87) 50.11,45.87 50.51,46.27 50.51,49.2 55.09,53.77 55.09,58.85 54.32,59.61 54.32,60.03 54.22,60.14 53.54,60.14 53.43,60.24 53.43,60.46 53.54,60.56 54.22,60.56 54.32,60.67 54.32,62.66 54.45,62.78 v1(55.09,62.78)
RGMII_TXD3: length 27.4
  TOP w0.14: v1(57.24,63.29) 57.63,63.67 58.26,63.67 59.36,62.57 U6.35 ; v1(52.55,48.56) 52.55,45.42 R79.1
  L08_SIG2 w0.107: v1(57.24,63.29) 56.99,63.55 56.48,63.55 55.47,62.53 55.47,51.43 55.36,51.32 54.81,51.32 54.7,51.21 54.7,51 54.81,50.89 55.36,50.89 55.59,50.66 55.59,49.32 55.28,49.01 52.74,49.01 52.55,48.81 v1(52.55,48.56)
RS232RX: length 9.7
  TOP w0.14: R142.2 R146.2 25.01,17.2 23.72,18.49 23.72,21.26 22.94,22.04 J3.55
RS232TX: length 17.6
  TOP w0.14: J3.57 22.93,21.54 23.34,21.13 23.34,18.22 24.87,16.68 29.59,16.68 31.24,18.33 31.24,19.1 32.04,19.9 R138.2 33.08,19.9 33.5,19.48 R139.2
SCL: length 6
  TOP w0.14: R141.2 24.24,18.84 24.1,18.98 24.1,21.76 23.33,22.54 J3.53
SD_CD: length 65.1
  TOP w0.14: U12.C15 v1(47.4,40.31)
  L08_SIG2 w0.107: v1(47.4,40.31) 47.01,39.92 46.32,39.92 46.2,39.8 46.2,39.29 46.04,39.13 43.94,39.13 43.82,39.25 43.82,42.37 45.56,44.11 45.56,59.86 46.11,60.42 46.11,65.37 46.57,65.83 63.08,65.83 v1(64.36,67.1)
  BOTTOM w0.14: J5.9 68.66,76.85 D15.1 R172.2 68.56,75.03 68.25,74.72 66.77,74.72 66.39,74.34 66.39,69.13 v1(64.36,67.1)
SD_CLK: length 68.1
  TOP w0.14: v1(42.82,45.87) 42.77,45.82 R72.2
  L08_SIG2 w0.107: v1(42.82,45.87) 42.82,68.55 49.17,74.9 56.03,74.9 57.75,76.63 58.39,76.63 58.64,76.37 58.64,74.21 58.9,73.96 61.31,73.96 61.56,74.21 61.56,76.37 62.07,76.88 63.59,76.88 65.63,74.85 v1(72.99,74.85)
  BOTTOM w0.14: J5.5 72.91,76.8 72.49,76.38 72.49,74.34 72.61,74.22 72.61,74.21 ; 72.61,74.21 U16.3 ; 72.61,74.21 72.71,74.31 72.71,74.56 v1(72.99,74.85)
SD_CMD: length 73.5
  TOP w0.14: R32.2 74.38,73.07 v1(73.37,72.06) ; U12.E9 v1(41.8,38.71)
  L08_SIG2 w0.107: v1(41.8,38.71) 42.22,39.13 42.76,39.13 43.5,39.87 43.5,42.5 45.2,44.21 45.2,65.6 48.26,68.66 73.4,68.66 74.52,69.77 74.52,71.8 74.26,72.06 v1(73.37,72.06)
  BOTTOM w0.14: J5.3 75.11,76.67 75.28,76.5 75.28,73.96 74.14,72.82 U16.6 73.11,72.32 v1(73.37,72.06)
SD_DAT0: length 73.1
  TOP w0.14: U12.D9 v1(41.8,39.51) ; R28.2 71.51,75.57 v1(71.6,75.48)
  L08_SIG2 w0.107: v1(41.8,39.51) 41.38,39.93 41.38,42.71 40.92,43.17 40.92,67.54 50.62,77.24 60.4,77.24 60.93,77.77 70.33,77.77 71.6,76.5 v1(71.6,75.48)
  BOTTOM w0.14: 72.11,74.24 72.11,74.24 72.21,74.34 72.21,75.89 70.71,77.39 J5.7 ; 72.11,74.24 U16.2 ; 72.11,74.24 72.01,74.34 72.01,74.48 71.89,74.6 71.89,75.19 v1(71.6,75.48)
SD_DAT1: length 73
  TOP w0.14: U12.C10 v1(42.6,40.31) ; R29.2 70.47,74.58 v1(70.71,74.34)
  L08_SIG2 w0.107: v1(70.71,74.34) 73.37,74.34 73.57,74.14 73.57,73.15 72.93,72.51 72.93,71.24 72.48,70.79 72.48,70.28 71.09,68.88 70.22,68.88 70.11,68.99 70.11,69.41 70,69.52 69.79,69.52 69.68,69.41 69.68,68.99 69.58,68.88 47.97,68.88 44.98,65.89 44.98,45.15 43.15,43.32 43.15,40.86 v1(42.6,40.31)
  BOTTOM w0.14: v1(70.71,74.34) 71.09,74.34 71.34,74.09 U16.1 71.61,74.58 71.34,74.85 69.94,74.85 69.61,75.19 J5.8
SD_DAT2: length 72.8
  TOP w0.14: v1(71.47,71.93) 71.25,71.71 R34.2 ; U12.A9 v1(41.8,41.91)
  L08_SIG2 w0.107: v1(41.8,41.91) 42.06,42.17 42.06,44.17 43.81,45.92 43.81,68.53 47.52,72.24 69.86,72.24 69.96,72.34 69.96,72.71 70.07,72.82 70.28,72.82 70.39,72.71 70.39,72.34 70.5,72.24 71.16,72.24 v1(71.47,71.93)
  BOTTOM w0.14: U16.8 72.11,72.69 ; 72.11,72.69 72.01,72.6 72.01,72.42 71.86,72.28 71.82,72.28 v1(71.47,71.93) ; 72.11,72.69 72.11,72.69 72.23,72.56 72.23,72.18 72.03,71.98 72.03,71.24 72.23,71.04 72.99,71.04 73.12,71.17 73.75,71.17 76.04,73.45 76.04,76.37 77.31,77.64 J5.1
SD_DAT3: length 74.5
  TOP w0.14: v1(72.48,71.55) 73.99,71.55 74.5,72.06 R33.2 ; U12.B9 v1(41.8,41.11)
  L08_SIG2 w0.107: v1(72.48,71.55) 72.1,71.55 71.6,71.04 71.06,71.04 70.95,70.93 70.95,69.88 70.84,69.77 70.63,69.77 70.52,69.88 70.52,70.93 70.42,71.04 46.96,71.04 44.03,68.11 44.03,45.51 42.38,43.86 42.38,41.69 v1(41.8,41.11)
  BOTTOM w0.14: 72.61,72.69 72.51,72.59 72.51,72.45 72.51,72.06 72.48,72.04 v1(72.48,71.55) ; 72.61,72.69 72.71,72.59 72.71,72.42 72.83,72.3 72.83,71.96 73.18,71.61 73.69,71.61 75.66,73.58 75.66,76.88 76.21,77.43 J5.2 ; 72.61,72.69 U16.7
SD_DETECT_LED5: length 80.9
  TOP w0.14: U12.D6 v1(39.4,39.51) ; LD2.1 v1(4.92,93.65)
  L03_SIG1 w0.107: v1(4.92,93.65) 4.92,91.23 3.4,89.71 3.4,70.28 5.81,67.86 13.05,67.86 23.08,57.83 32.61,57.83 34.95,55.49 34.95,44.16 38.82,40.29 38.82,40.1 v1(39.4,39.51)
SD_FULL_LED0: length 78.5
  TOP w0.14: LD3.1 v1(6.7,93.65) ; U12.C9 v1(41.8,40.31)
  L03_SIG1 w0.107: v1(41.8,40.31) 42.22,40.73 42.22,59.01 41.75,59.48 41.75,71.42 41.12,72.06 25.88,72.06 6.7,91.23 v1(6.7,93.65)
SD_STORE: length 54.5
  TOP w0.14: SW2.2 12.67,72.56 12.9,72.79 v1(13.18,72.79) ; U12.C7 v1(40.2,40.31)
  L03_SIG1 w0.107: v1(40.2,40.31) 40.17,40.35 40.17,40.61 37.81,42.96 37.81,56.31 34.38,59.74 24.22,59.74 15.46,68.5 15.46,72.69 14.83,73.33 13.71,73.33 v1(13.18,72.79)
  BOTTOM w0.14: R174.2 12.67,72.56 12.9,72.79 v1(13.18,72.79)
SDA: length 5.2
  TOP w0.14: R136.2 24.61,20.06 24.61,22.02 23.59,23.04 J3.51
SPARE_GPIO_SW: length 46.4
  TOP w0.14: v1(35.27,29.13) 35.66,29.51 U12.T1 ; R159.1 C95.2 R160.2 v1(13.41,6.76)
  L08_SIG2 w0.107: v1(13.41,6.76) 13.81,7.16 13.81,11.35 15.59,13.13 32.35,13.13 33.88,14.65 33.88,18.97 32.48,20.37 32.48,23.03 34.13,24.68 34.13,27.48 35.27,28.62 v1(35.27,29.13)
SPARE_LED8: length 83.1
  TOP w0.14: U12.E7 v1(40.2,38.71) ; LD4.1 v1(8.48,93.65)
  L03_SIG1 w0.107: v1(8.48,93.65) 8.48,92.76 9.75,91.49 9.75,89.2 25.81,73.14 41.81,73.14 42.76,72.19 42.76,46.66 43.25,46.17 43.25,42.6 43.04,42.39 43.04,40.22 42.76,39.93 42.48,39.93 42.22,39.67 42.22,38.59 41.96,38.33 40.58,38.33 v1(40.2,38.71)
SPI_CS_N: length 38.9
  TOP w0.14: U12.R2 v1(36.2,29.91) ; R156.1 v1(56.74,8.05)
  L08_SIG2 w0.107: v1(56.74,8.05) 47.97,16.81 38.19,16.81 34.51,20.49 34.51,27.35 36.2,29.04 v1(36.2,29.91)
SPI_HOLD_N: length 18.3
  TOP w0.14: U12.W1 v1(35.4,26.71) ; R148.1 v1(46.28,19.14)
  L08_SIG2 w0.107: v1(35.4,26.71) 35.4,22.02 37.94,19.48 45.94,19.48 v1(46.28,19.14)
SPI_MISO: length 41.1
  TOP w0.14: U12.V2 v1(36.2,27.51) ; R157.1 v1(61.31,8.05)
  L08_SIG2 w0.107: v1(61.31,8.05) 57.37,8.05 48.35,17.06 38.45,17.06 34.77,20.75 34.77,21.51 34.89,21.64 34.89,27.22 35.18,27.51 v1(36.2,27.51)
SPI_MOSI: length 26.4
  TOP w0.14: R126.1 52.04,22.91 51.66,23.29 49.37,23.29 48.74,22.65 v1(48.74,19.86) ; U12.W2 v1(36.2,26.71)
  L08_SIG2 w0.107: v1(48.74,19.86) 48.61,19.73 38.07,19.73 35.78,22.02 35.78,26.29 v1(36.2,26.71)
SPI_SCK: length 37.4
  TOP w0.14: v1(48.99,14.65) 49.75,15.41 49.75,21.26 50.09,21.6 R125.2 U14.16
  L08_SIG2 w0.107: v1(33.11,21.13) 33.24,21.13 35.15,19.22 35.15,16.81 37.31,14.65 v1(48.99,14.65)
  BOTTOM w0.14: R213.1 33.46,24.26 32.48,23.29 32.48,21.76 v1(33.11,21.13)
SPI_WP_N: length 33.4
  TOP w0.14: R127.1 62.49,22.49 62.2,22.78 57.24,22.78 56.48,22.02 v1(56.48,20.75) ; U12.Y2 36.2,25.91 v1(36.2,25.66)
  L08_SIG2 w0.107: v1(56.48,20.75) 56.18,20.44 40.28,20.44 39.72,21 38.19,21 36.2,22.99 v1(36.2,25.66)
SYS_CLK100_N: length 5.1
  TOP w0.14: U12.F1 35.17,38.15 33.88,38.15 33.46,38.57 R88.2 32.52,38.57 32.23,38.27 U9.5
SYS_CLK100_P: length 6
  TOP w0.14: U12.G2 36.2,37.12 35.54,37.12 34.93,37.73 R88.1 32.44,37.73 31.94,37.22 U9.4
USB1_CS: length 18.4
  TOP w0.14: U15.63 v1(74.97,6.45)
  BOTTOM w0.14: v1(74.97,6.45) 74.97,13.69 73.25,15.41 69.18,15.41 68.93,15.66 R218.2 U20.1
USB1_DI: length 15.1
  TOP w0.14: U15.61 v1(73.97,6.43)
  BOTTOM w0.14: v1(73.97,6.43) 73.97,11.89 72.4,13.47 R220.2 U20.3
USB1_DO: length 3.3
  BOTTOM w0.14: R221.2 69.02,11.94 69,11.95 R220.1 68.43,12.63 68,12.2 U20.4
USB1_SCK: length 15
  TOP w0.14: U15.62 v1(74.47,7.33)
  BOTTOM w0.14: v1(74.47,7.33) 74.47,12.66 72.99,14.14 69.18,14.14 68.94,14.39 R219.2 U20.2
USB2_CS: length 7.9
  TOP w0.14: U4.1 84.04,73.51 83.9,73.65 R31.2 83.4,74.2 83.28,74.32 83.28,75.58 83.12,75.74 82.01,75.74 81.7,76.04 U3.63
USB2_DI: length 11.4
  TOP w0.14: U3.61 80.7,71.84 81.57,70.97 R35.2 U4.3
USB2_DO: length 3.5
  TOP w0.14: U4.4 84.38,69.7 83.95,70.13 R35.1 R37.2
USB2_SCK: length 9.5
  TOP w0.14: U3.62 81.2,74.89 81.86,74.24 R30.2 82.73,72.61 83.09,72.24 U4.2
USER_SW1: length 60.6
  TOP w0.14: U12.B8 v1(41,41.11) ; SW2.6 7.59,72.54 v1(7.33,72.79)
  L03_SIG1 w0.107: v1(41,41.11) 41,41.37 40.62,41.75 40.62,41.76 40.6,41.77 40.6,42.65 39.75,43.5 39.75,58.31 37.11,60.95 32.29,60.95 18.13,75.1 9.65,75.1 v1(7.33,72.79)
  BOTTOM w0.14: R178.2 7.59,72.54 v1(7.33,72.79)
USER_SW2: length 61.7
  TOP w0.14: v1(6.42,72.82) 6.32,72.72 SW2.7 ; U12.A8 v1(41,41.91)
  L03_SIG1 w0.107: v1(41,41.91) 41,42.35 40.94,42.41 40.94,43.61 40.05,44.5 40.05,58.9 37.56,61.39 32.73,61.39 18.38,75.74 9.34,75.74 v1(6.42,72.82)
  BOTTOM w0.14: R179.2 6.32,72.72 v1(6.42,72.82)
USER_SW3: length 66.9
  TOP w0.14: v1(5.51,72.82) 5.19,72.82 5.05,72.68 SW2.8 ; U12.D8 v1(41,39.51)
  L03_SIG1 w0.107: v1(41,39.51) 41.38,39.89 41.38,42.58 41.26,42.7 41.26,43.84 41.12,43.98 41.12,58.47 37.81,61.77 33.11,61.77 18.51,76.37 9.06,76.37 v1(5.51,72.82)
  BOTTOM w0.14: v1(5.51,72.82) 5.19,72.82 5.05,72.68 R180.2
N35954: length 5.1
  TOP w0.14: R42.2 J6.1
N35962: length 3.9
  TOP w0.14: R70.2 J6.11
N36046: length 3.1
  TOP w0.14: J6.14 95.52,63.16 95.52,64.87 95.73,65.07 R40.2
N40882: length 10.5
  TOP w0.14: U6.19 68.63,67.44 69.69,68.5 71.34,68.5 71.91,69.07 R38.1 C44.1 74.54,69.07 75.74,70.27 Y2.1
N40902: length 9.9
  TOP w0.14: U6.18 69.13,67.54 69.81,68.22 71.37,68.22 71.91,67.67 R38.2 C51.1 74.54,67.67 75.74,66.47 Y2.2
N41020: length 3.5
  TOP w0.14: v1(67.28,66.98) 67.28,66.47 67.15,66.34 67.15,65.54 U6.22
  BOTTOM w0.14: v1(67.28,66.98) 67.28,65.71 67.02,65.45 R182.2
N41650: length 24.7
  TOP w0.14: v1(73.37,51.86) 71.9,53.33 69.87,53.33 69.63,53.57 U6.64 ; v1(71.85,66.09) 71.21,66.72 69.83,66.72 69.63,66.52 U6.17
  L08_SIG2 w0.107: v1(71.85,66.09) 72.74,65.2 72.74,52.5 v1(73.37,51.86)
  BOTTOM w0.14: v1(73.37,51.86) 73.75,51.86 TP11.1
N44878: length 3.8
  TOP w0.14: U6.15 72.39,63.07 72.61,63.29 72.61,64.18 73.12,64.69 R44.1
N70149: length 7.5
  TOP w0.14: R155.1 84.17,12.68 83.85,13 79.22,13 79.21,12.99 U15.6
N70296: length 3.6
  TOP w0.14: R145.2 79.88,18.23 78.63,16.99 U15.14
N76086: length 4
  TOP w0.14: U15.16 78.83,17.99 79.34,18.5 79.34,19.1 79.59,19.34 R140.1
N76092: length 3.3
  TOP w0.14: U15.17 75.47,21.83 75.79,22.14 R124.1
N76288: length 4.7
  TOP w0.14: U15.18 74.97,22.6 75.66,23.29 R121.1
N76294: length 6.2
  TOP w0.14: R118.1 75.53,24.43 74.64,23.54 74.64,21.05 74.52,20.92 74.52,19.99 U15.19
N77950: length 1.4
  TOP w0.14: LD15.2 R154.2
N12057923: length 2.1
  BOTTOM w0.14: R209.2 R210.2 74.77,35.95 C163.1
N12082124: length 3.6
  TOP w0.14: U12.U3 v1(37,28.31)
  BOTTOM w0.14: R213.2 35.22,27.61 35.53,27.92 36.6,27.92 v1(37,28.31)
N12141516: length 5.5
  TOP w0.14: U3.6 85.46,82.45 86.26,81.65 88.69,81.65 89.11,82.06 R25.2
N12141647: length 3.6
  TOP w0.14: R20.2 85.64,88.39 85.44,88.18 85.44,86.79 85.1,86.45 U3.14
N12198012: length 3
  TOP w0.14: U8.1 37.25,50.01 37.05,50.21 R53.2 R54.2
N12285548: length 5.5
  TOP w0.14: R98.2 24.99,33.83 23.69,32.54 J3.13
N12367018: length 6.2
  TOP w0.14: v1(42.92,22.53) 43.24,22.84 43.24,26.55 U12.W11
  BOTTOM w0.14: TP17.1 43.55,21.89 v1(42.92,22.53)
N12367024: length 7.4
  TOP w0.14: U12.W10 42.71,26.82 42.71,23.92 42.47,23.68 42.47,21.91 v1(42.92,21.46)
  BOTTOM w0.14: TP20.1 42.83,20.18 42.92,20.27 v1(42.92,21.46)
N12367080: length 5.7
  TOP w0.14: U12.W4 v1(37.8,26.71)
  BOTTOM w0.14: v1(37.8,26.71) 37.8,26.18 37.71,26.09 37.71,26.06 35.91,24.26 TP14.1
N12367084: length 8
  TOP w0.14: U12.W5 v1(38.6,26.71)
  L03_SIG1 w0.107: v1(37.18,21.38) 37.18,25.03 38.6,26.45 v1(38.6,26.71)
  BOTTOM w0.14: v1(37.18,21.38) 36.86,21.07 TP23.1
N12367136: length 11.1
  TOP w0.14: U12.W8 v1(41,26.71)
  BOTTOM w0.14: TP22.1 38.3,20.52 38.3,21.03 36.8,22.53 36.8,24.56 38.07,25.83 38.07,25.94 38.44,26.31 38.48,26.31 38.49,26.32 40.6,26.32 v1(41,26.71)
N12367140: length 7.8
  TOP w0.14: U12.W9 42.2,26.15 41.81,25.76 41.81,24.49 40.58,23.26 v1(40.58,21.51)
  BOTTOM w0.14: TP21.1 40.58,20.39 v1(40.58,21.51)
N12367168: length 7.3
  TOP w0.14: U12.W13 45.56,26.96 45.56,21.76 v1(45.26,21.46)
  BOTTOM w0.14: TP19.1 45.26,20.32 v1(45.26,21.46)
N12367248: length 6.5
  TOP w0.14: U12.W14 v1(46.6,26.71)
  BOTTOM w0.14: v1(46.6,26.71) 45.94,26.71 45.56,26.34 45.56,22.53 TP16.1
N12367252: length 8.6
  TOP w0.14: U12.W17 49.45,26.27 49.45,25.14 47.08,22.78 47.08,21.97 v1(47.59,21.46)
  BOTTOM w0.14: v1(47.59,21.46) 47.59,20.37 TP18.1
N12367256: length 6.8
  TOP w0.14: U12.W18 49.8,26.71 49.8,24.74 v1(47.59,22.53)
  BOTTOM w0.14: v1(47.59,22.53) 48.23,21.89 TP15.1
N12556752: length 3.8
  TOP w0.14: R6.2 72.61,89.84 73.1,89.35 U3.32
N12556756: length 2.2
  TOP w0.14: U3.34 R22.2
N12556864: length 2.2
  TOP w0.14: U3.27 77.2,91.05 R5.2
N12556868: length 2.2
  TOP w0.14: U3.28 76.7,91.12 R4.2
N12563455: length 1.9
  TOP w0.14: U3.45 71.66,81.45 71.13,80.92 R26.2
N15277458: length 3.5
  TOP w0.14: U5.5 52.58,65.54 52.72,65.68 53.46,65.68 53.69,65.45 53.69,64.83 53.83,64.69 R43.2
N15277487: length 3.6
  TOP w0.14: U5.6 51.93,65.69 52.2,65.96 54.56,65.96 C53.1
N15279182: length 4.1
  TOP w0.14: U5.3 51.93,60.56 C58.2 R45.2 54.24,60.45 R46.1
N15280631: length 8.7
  TOP w0.381: R16.1 R1.1 ; R1.1 29.55,92.38 29.13,91.96 C2.1 29.13,89.84 28.99,89.71 U1.4 ; R1.1 30.19,92.73 30,92.92 R8.1
N15281998: length 1.9
  TOP w0.14: U1.3 29.64,89.51 30.18,90.05 R16.2
N15282067: length 4
  TOP w0.14: R8.2 28.28,92.08 27.69,91.5 U1.6
N15282531: length 2.3
  TOP w0.14: C12.1 31,90.01 30.29,89.3 U1.2
N15282538: length 3.7
  TOP w0.14: U1.7 C1.1
N15283211: length 0.9
  TOP w0.457: U1.9 26.4,82.97 26,83.36
N15283215: length 1.1
  TOP w0.457: U1.16 30.94,83.35 31.21,83.61
N15294700: length 1.1
  TOP w0.457: U2.16 55.71,83.35 55.97,83.61
N15294712: length 0.9
  TOP w0.457: 50.77,83.36 51.16,82.97 U2.9
N15294756: length 8.1
  TOP w0.381: R2.1 54.2,92.12 53.64,91.57 C4.1 53.76,90.35 U2.4 ; R2.1 54.79,92.54 54.41,92.92 R9.1 ; R2.1 54.79,92.12 R17.1
N15294840: length 1.9
  TOP w0.14: U2.3 54.41,89.41 54.79,89.79 R17.2
N15294864: length 4.2
  TOP w0.14: R9.2 52.16,91.19 52.16,89.71 52.46,89.41 U2.6
N15294982: length 2
  TOP w0.14: U2.2 55.06,89.11 C13.1
N15294990: length 3.7
  TOP w0.14: U2.7 C3.1
N15331843: length 4.7
  BOTTOM w0.14: R207.1 C148.2 R211.2 95.6,35.61 95.34,35.35 94.55,35.35 94.31,35.59 U19.1
N15331979: length 1.5
  BOTTOM w0.14: R202.2 92.55,39.74 92.81,39.47 U19.7
N15358263: length 2.5
  TOP w0.14: R83.2 28.42,39.54 28.64,39.32 U9.1
N15366217: length 1.6
  TOP w0.14: LD11.2 v1(6.53,40.77)
  BOTTOM w0.14: v1(6.53,40.77) 6.49,40.81 R87.2
N15366273: length 1.9
  TOP w0.14: LD13.2 v1(5.87,35.1)
  BOTTOM w0.14: v1(5.87,35.1) 5.87,34.49 R93.2
N15366361: length 1.5
  TOP w0.14: LD14.2 R103.2
N15366449: length 2.6
  TOP w0.14: LD14.1 89.45,29.18 89.25,29.38 89.25,29.76 89.07,29.94 Q1.3
N15366479: length 2.8
  TOP w0.14: R104.1 83.87,30.6 84.15,30.89 Q1.1
N15371882: length 8.8
  TOP w0.14: R151.2 D12.1 6.12,15.29 5.36,16.06 SW5.2 5.36,16.49 5.94,17.06 5.94,19.6 5.36,20.18 SW5.1
N15373103: length 8.9
  TOP w0.14: SW7.1 15.65,9.38 16.35,10.08 18.64,10.08 19.34,9.38 SW7.2 20.61,9.38 21.03,8.95 D14.1 R161.2
N15375282: length 9.1
  TOP w0.14: R159.2 D13.1 8.6,9.34 8.22,9.72 SW6.2 7.16,9.72 6.73,10.14 3.84,10.14 3.41,9.72 SW6.1
N15376242: length 8.8
  TOP w0.14: SW4.1 5.36,31.47 4.92,31.03 4.92,28.24 5.36,27.8 SW4.2 5.36,27.42 6.38,26.4 D10.1 R114.2
N15385918:
  vias: v1(96.61,19.35) v1(96.61,18.21) v1(97.38,29.76) v1(97.38,28.49) v1(98.01,18.21) v1(98.77,29.76) v1(98.77,28.49) v1(99.41,18.21) v1(100.3,29.76) v1(100.3,28.49)
N15385952: length 3.6
  TOP w0.14: J4.1 95.64,21.93 v1(95.34,21.64)
  BOTTOM w0.14: TP30.1 v1(95.34,21.64)
N15394436: length 5.7
  TOP w0.14: J1.1 95.29,70.08 94.84,70.53 v1(93.31,70.53)
  BOTTOM w0.14: TP31.1 v1(93.31,70.53)
N15394548:
  vias: v1(96.36,77.9) v1(96.36,75.99) v1(97.76,66.47) v1(97.76,65.45) v1(98.14,77.9) v1(98.14,75.99) v1(99.28,66.47) v1(99.28,65.45) v1(100.04,77.9)
N15403136: length 1.3
  TOP w0.14: U13.4 R143.1
N15568992: length 1.3
  TOP w0.14: U11.H8 v1(72.1,38.08)
  BOTTOM w0.14: v1(72.1,38.08) 72.04,38.02 R205.1
N15578317: length 1.7
  TOP w0.14: U10.H8 v1(60.29,38.08)
  BOTTOM w0.14: R206.1 59.78,38.02 59.84,38.08 v1(60.29,38.08)
N15683813: length 6.8
  BOTTOM w0.14: TP10.1 84.8,64.94 84.6,64.74 J6.2
N15696938: length 2.9
  TOP w0.14: U3.26 77.7,90.61 77.95,90.85 78.58,90.85 78.72,90.99 R3.2
N15697022: length 5.2
  TOP w0.14: U12.C13 v1(45.8,40.31) ; R76.2 v1(47.35,43.61)
  L08_SIG2 w0.107: v1(47.35,43.61) 47.35,43.23 46.2,42.08 46.2,40.94 45.8,40.55 v1(45.8,40.31)
N15697026: length 8.6
  TOP w0.14: U12.D13 v1(45.8,39.51) ; v1(48.66,43.53) 48.66,44.26 R81.2
  L08_SIG2 w0.107: v1(45.8,39.51) 45.41,39.91 45.41,42.19 46.45,43.23 46.58,43.23 46.83,43.48 46.83,43.73 47.21,44.12 48.08,44.12 v1(48.66,43.53)
N15801768: length 7.4
  TOP w0.14: v1(43.99,43.53) 43.91,43.61 R73.2 ; U12.E11 v1(44.2,38.71)
  BOTTOM w0.14: v1(43.99,43.53) 43.27,42.82 43.27,40.68 44.04,39.92 44.36,39.92 44.6,39.68 44.6,39.11 v1(44.2,38.71)
N15802042: length 5.3
  TOP w0.14: U12.B19 52.8,43.31 52.8,44.24 52.89,44.33 R80.2
N15802046: length 3.5
  TOP w0.14: U12.A18 51.15,43.26 R78.2
N15802050: length 4.9
  TOP w0.14: U12.C17 v1(49,40.31) ; R77.2 49.88,43.58 v1(49.83,43.53)
  L08_SIG2 w0.107: v1(49,40.31) 49.38,40.69 49.38,41.58 49.83,42.02 v1(49.83,43.53)
N15802054: length 5.5
  TOP w0.14: R79.2 52.29,43.66 v1(51.76,43.13) ; U12.B18 v1(49.8,41.11)
  L08_SIG2 w0.107: v1(49.8,41.11) 49.88,41.19 50.51,41.19 51.15,41.83 51.15,43.02 51.26,43.13 v1(51.76,43.13)
N15802227: length 3.8
  TOP w0.14: U12.B12 45,41.11 45,44.28 R74.2
N15802298: length 5.2
  TOP w0.14: v1(46.32,43.61) 46.2,43.73 R75.2 ; U12.C12 v1(45,40.31)
  L08_SIG2 w0.107: v1(46.32,43.61) 45,42.29 v1(45,40.31)
N15837314: length 1.6
  TOP w0.14: LD12.2 v1(6.53,38.74)
  BOTTOM w0.14: v1(6.53,38.74) 6.49,38.78 R89.2
N15837897: length 3.9
  TOP w0.14: v1(42.82,43.53) 42.77,43.58 R72.1 ; U12.B10 v1(42.6,41.11)
  BOTTOM w0.14: v1(42.6,41.11) 42.64,41.15 42.64,43.35 v1(42.82,43.53)
N15863331: length 1.5
  TOP w0.14: v1(6.7,90.6) LD3.2
  BOTTOM w0.14: R169.1 v1(6.7,90.6)
N15864243: length 1.5
  TOP w0.14: LD1.2 v1(3.02,90.6)
  BOTTOM w0.14: R171.1 v1(3.02,90.6)
N15865404: length 1.5
  TOP w0.14: LD5.2 v1(12.29,90.6)
  BOTTOM w0.14: R167.1 v1(12.29,90.6)
N15865498: length 1.5
  TOP w0.14: v1(14.19,90.6) LD7.2
  BOTTOM w0.14: R165.1 v1(14.19,90.6)
N15865593: length 1.5
  TOP w0.14: LD8.2 v1(17.37,90.6)
  BOTTOM w0.14: R164.1 v1(17.37,90.6)
N15870131: length 1.5
  TOP w0.14: v1(4.92,90.6) LD2.2
  BOTTOM w0.14: R170.1 v1(4.92,90.6)
N15870370: length 1.5
  TOP w0.14: v1(19.27,90.6) LD9.2
  BOTTOM w0.14: R163.1 v1(19.27,90.6)
N15870464: length 1.5
  TOP w0.14: LD6.2 v1(10.38,90.6)
  BOTTOM w0.14: R166.1 v1(10.38,90.6)
N15870575: length 1.5
  TOP w0.14: LD4.2 v1(8.48,90.6)
  BOTTOM w0.14: R168.1 v1(8.48,90.6)
N16168033: length 33.1
  TOP w0.14: U12.A2 v1(36.2,41.11)
  L03_SIG1 w0.107: v1(10,40.94) 15.08,46.02 33.37,46.02 33.75,45.64 33.75,43.57 v1(36.2,41.11)
  BOTTOM w0.14: TP27.1 v1(10,40.94)
N16168037: length 32.3
  TOP w0.14: v1(35.4,41.19) 35.8,40.79 U12.B1
  L03_SIG1 w0.107: v1(35.4,41.19) 32.73,43.86 32.73,44.24 32.1,44.88 15.84,44.88 11.27,40.31 9.37,40.31 v1(8.86,39.8)
  BOTTOM w0.14: v1(8.86,39.8) TP28.1
N16178955: length 8.6
  TOP w0.14: U12.V1 34.96,27.07 34.96,24.87 35.27,24.56 v1(35.27,21.26)
  BOTTOM w0.14: v1(35.27,21.26) 34.89,20.87 TP29.1
N16278938: length 1.7
  TOP w0.14: LD10.1 v1(37.18,93.52)
  BOTTOM w0.14: R21.1 v1(37.18,93.52)
N16403293: length 3.2
  TOP w0.14: U14.7 R156.2 R158.2
N16403351: length 10.3
  TOP w0.14: U14.1 50.77,11.73 48.35,14.14 R149.2 R148.2
N16403393: length 4.1
  TOP w0.14: U14.9 59.66,20.08 60.07,20.49 R131.2 R127.2
N16403481: length 2.2
  TOP w0.14: R126.2 U14.15
N16403515: length 2.1
  TOP w0.14: U14.8 R157.2

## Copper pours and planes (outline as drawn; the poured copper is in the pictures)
1V1 on TOP: 57.3,60.15 57.55,60.15 58.22,59.49 58.22,59.37 58.22,59.37 58.22,58.75 58.26,58.7 58.26,58.23 57.92,57.89 57.24,57.89 57.19,57.94 57.19,60.04
